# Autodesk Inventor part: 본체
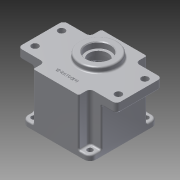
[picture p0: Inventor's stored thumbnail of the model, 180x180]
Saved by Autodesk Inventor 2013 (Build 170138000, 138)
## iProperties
Created: 2015-07
Part Number: 본체
Material: 알루미늄 6061
Document SubType Name: Modeling
Designer: user
Density: 2.71 g/cm^3
Mass: 705.36 g
Surface Area: 672.968 cm^2
Volume: 260.28 cm^3
Author: user
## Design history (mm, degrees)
sketch "스케치1"
  geometry: L1 (-65, 30)-(65, 30); L2 (65, 30)-(65, -30); L3 (65, -30)-(-65, -30); L4 (-65, -30)-(-65, 30); L5 (-30, 45)-(30, 45); L6 (30, 45)-(30, -45); L7 (30, -45)-(-30, -45); L8 (-30, -45)-(-30, 45); 5 further points
  constraints: 16 end point, 4 midpoint, 4 parallel, 2 horizontal, 2 horizontal alignment, 2 perpendicular, 2 vertical alignment
  dimensions: "d0" = 130 distance of L2.end L3.end; "d1" = 60 distance of L1.end L2.end; "d2" = 60 distance of L6.end L7.end; "d3" = 90 distance of L5.end L6.end
extrude "돌출1" new body sketch "스케치1" distance "d4" = 12; taper "d5" = 0 deg
sketch "스케치2"
  geometry: L1 (-45, -45)-(45, -45); L2 (45, -45)-(45, 45); L3 (45, 45)-(-45, 45); L4 (-45, 45)-(-45, -45); 3 further points
  constraints: 8 end point, 2 midpoint, 2 parallel, 1 horizontal, 1 horizontal alignment, 1 perpendicular, 1 vertical alignment
  dimensions: "d6" = 90 distance of L3.end L2.end; "d7" = 90 distance of L2.end L1.end
extrude "돌출2" join sketch "스케치2" distance "d8" = 58; taper "d9" = 0 deg
sketch "스케치3"
  geometry: L1 (30, 45)-(30, 30) reference; L2 (-45, -45)-(-45, -30) reference; L3 (-30, -30)-(-45, -30) reference; L4 (-30, -45)-(-30, -30) reference; L5 (30, -45)-(-30, -45) reference; L6 (30, -30)-(30, -45) reference; L7 (45, -30)-(30, -30) reference; L8 (45, 30)-(45, -30) reference; L9 (45, 30)-(65, 30) reference; L10 (65, 30)-(65, -30) reference; L11 (65, -30)-(45, -30) reference; L12 (45, -30)-(45, -45) reference; L13 (45, -45)-(30, -45) reference; L14 (-30, -45)-(-45, -45) reference; L15 (-45, -30)-(-45, 30) reference; L16 (-65, 30)-(-45, 30) reference; L17 (-65, -30)-(-65, 30) reference; L18 (-45, -30)-(-65, -30) reference; L19 (45, 45)-(45, 30) reference; L20 (30, 30)-(45, 30) reference; L21 (30, 45)-(30, 30) reference; L22 (30, 45)-(45, 45) reference; L23 (-45, 30)-(-45, 45) reference; L24 (-45, 45)-(-30, 45) reference; L25 (-30, 45)-(30, 45) reference; L26 (-45, 30)-(-30, 30) reference; L27 (-30, 30)-(-30, 45) reference; 1 further point
extrude "돌출3" cut sketch "스케치3" distance "d10" = 51; taper "d11" = 0 deg
sketch "스케치4"
  geometry: C1 r 40 at (0, 0); 1 further point
  constraints: 1 centre point, 1 coincident
  dimensions: "d12" = 80 diameter of C1
extrude "돌출4" cut sketch "스케치4" distance "d13" = 9; taper "d14" = 0 deg
sketch "스케치5"
  geometry: C1 r 40 at (0, 0) reference; C2 r 39 at (0, 0)
  constraints: 1 centre point, 1 coincident
  dimensions: "d15" = 78 diameter of C2
extrude "돌출5" cut sketch "스케치5" distance "d16" = 52; taper "d17" = 0 deg
sketch "스케치6"
  geometry: L1 (30, -45)-(30, -30) reference; L2 (0, 0)-(0, 11); C1 r 25 at (0, 11)
  constraints: 2 end point, 1 centre point, 1 parallel
  dimensions: "d18" = 50 diameter of C1; "d19" = 11 distance of L2.end L2.start
extrude "돌출6" join sketch "스케치6" distance "d21" = 7; taper "d22" = 0 deg
sketch "스케치7"
  geometry: L1 (0, 0)-(0, 11); L2 (0, 0)-(0, -20); C1 r 39 at (0, 0) reference; A1 r 20.5 centre (0, 11) between (7.402, -8.117) and (-7.402, -8.117); A2 r 14 centre (0, -20) between (-7.402, -8.117) and (7.402, -8.117)
  constraints: 4 end point, 4 point on circle, 2 centre point, 2 coincident, 1 collinear, 1 vertical
  dimensions: "d23" = 11 distance of L1.start L1.end; "d24" = 41 diameter of A1; "d25" = 20 distance of L1.start L2.end; "d26" = 28 diameter of A2
extrude "돌출7" join sketch "스케치7" distance "d27" = 7; taper "d28" = 0 deg
sketch "스케치8"
  geometry: C1 r 25 at (0, 0) reference; C2 r 16 at (0, 0); 1 further point
  constraints: 1 centre point, 1 coincident
  dimensions: "d29" = 32 diameter of C2
extrude "돌출8" cut sketch "스케치8" distance "d30" = 8; taper "d31" = 0 deg
sketch "스케치9"
  geometry: C1 r 16 at (0, 0) reference; C2 r 12.5 at (0, 0); 1 further point
  constraints: 1 centre point, 1 coincident
  dimensions: "d32" = 25 diameter of C2
extrude "돌출9" cut sketch "스케치9" distance "d33" = 5; taper "d34" = 0 deg
sketch "스케치10"
  geometry: C1 r 17.5 at (0, 11); A1 r 20.5 centre (0, 11) between (7.402, -8.117) and (-7.402, -8.117) reference; 1 further point
  constraints: 1 centre point, 1 coincident
  dimensions: "d35" = 35 diameter of C1
extrude "돌출10" cut sketch "스케치10" distance "d36" = 10; taper "d37" = 0 deg
sketch "스케치11"
  geometry: C1 r 11 at (0, -20); A1 r 14 centre (0, -20) between (-7.402, -8.117) and (7.402, -8.117) reference; 1 further point
  constraints: 1 centre point, 1 coincident
  dimensions: "d38" = 22 diameter of C1
extrude "돌출11" cut sketch "스케치11" distance "d39" = 7; taper "d40" = 0 deg
sketch "스케치12"
  geometry: C1 r 11 at (0, 0) reference; C2 r 9.5 at (0, 0); 1 further point
  constraints: 1 centre point, 1 coincident
  dimensions: "d41" = 19 diameter of C2
extrude "돌출12" cut sketch "스케치12" distance "d42" = 1; taper "d43" = 0 deg
sketch "스케치13"
  geometry: L1 (0, 0)-(24.749, 24.749); L2 (0, 0)-(35, 0); L3 (0, 0)-(24.749, -24.749); L4 (0, 0)-(35, 0); L5 (0, 0)-(-24.749, 24.749); L6 (0, 0)-(-24.749, -24.749); L7 (0, 0)-(0, -14.324); L8 (0, 0)-(-22.714, 0); C1 r 40 at (0, 0) reference; C2 r 4 at (24.749, 24.749); C3 r 4 at (-24.749, -24.749); C4 r 4 at (24.749, -24.749); C5 r 4 at (-24.749, 24.749); A1 r 39 centre (0, 0) between (21.134, 32.777) and (32.777, 21.134) reference; A2 r 3.5 centre (19.238, 29.836) between (21.762, 27.412) and (21.134, 32.777); A3 r 3.5 centre (29.836, 19.238) between (32.777, 21.134) and (27.412, 21.762); A4 r 3.5 centre (29.836, -19.238) between (27.412, -21.762) and (32.777, -21.134); A5 r 3.5 centre (19.238, -29.836) between (21.134, -32.777) and (21.762, -27.412); A6 r 3.5 centre (-29.836, -19.238) between (-32.777, -21.134) and (-27.412, -21.762); A7 r 3.5 centre (-19.238, -29.836) between (-21.762, -27.412) and (-21.134, -32.777); A8 r 3.5 centre (-29.836, 19.238) between (-27.412, 21.762) and (-32.777, 21.134); A9 r 3.5 centre (-19.238, 29.836) between (-21.134, 32.777) and (-21.762, 27.412); A10 r 35 centre (0, 0) between (-27.412, -21.762) and (-21.762, -27.412); A11 r 35 centre (0, 0) between (21.762, -27.412) and (27.412, -21.762); A12 r 35 centre (0, 0) between (27.412, 21.762) and (21.762, 27.412); A13 r 35 centre (0, 0) between (-21.762, 27.412) and (-27.412, 21.762); A14 r 39 centre (0, 0) between (21.134, -32.777) and (32.777, -21.134); A15 r 39 centre (0, 0) between (32.777, 21.134) and (21.134, 32.777); A16 r 39 centre (0, 0) between (-21.134, 32.777) and (-32.777, 21.134); A17 r 39 centre (0, 0) between (-32.777, -21.134) and (-21.134, -32.777)
  constraints: 38 point on circle, 20 centre point, 18 symmetric about line, 16 end point, 5 tangent, 3 coincident, 3 perpendicular, 2 equal length, 2 horizontal, 1 collinear, 6 other
  dimensions: "d45" = 8 diameter of C2; "d46" = 45 deg angle of L2 L1; "d47" = 8 diameter of C3; "d48" = 45 deg angle of L3 L4; "d49" = 8 diameter of C4; "d50" = 8 diameter of C5; "d51" = 7 diameter of A2; "d52" = 7 diameter of A3; "d53" = 10.12841 distance from line of L7.end L1; "d54" = 16.06109 distance from line of L8.end L1
extrude "돌출13" join sketch "스케치13" stored distance "d55" = 1; taper "d56" = 0 deg
fillet "모깎기1" dims "d57" = 3
fillet "모깎기2" dims "d58" = 0.3
fillet "모깎기3" dims "d59" = 0.3
fillet "모깎기4" dims "d60" = 2
chamfer "모따기1" distance "d61" = 1; stored, may be unused: second distance "d62" = 2, angle "d63" = 45 deg
fillet "모깎기5" dims "d64" = 8
fillet "모깎기6" dims "d65" = 5
fillet "모깎기7" dims "d66" = 5
sketch "스케치14"
  geometry: L1 (-37, -37)-(37, -37); L2 (37, -37)-(37, 37); L3 (37, 37)-(-37, 37); L4 (-37, 37)-(-37, -37); C1 r 3.5 at (37, 37); C2 r 3.5 at (37, -37); C3 r 3.5 at (-37, -37); C4 r 3.5 at (-37, 37); 3 further points
  constraints: 8 end point, 4 centre point, 4 coincident, 2 midpoint, 2 parallel, 1 horizontal, 1 horizontal alignment, 1 perpendicular, 1 vertical alignment
  dimensions: "d67" = 74 distance of L3.end L2.end; "d68" = 74 distance of L2.end L1.end; "d69" = 7 diameter of C1; "d70" = 7 diameter of C2; "d71" = 7 diameter of C3; "d72" = 7 diameter of C4
extrude "돌출14" cut sketch "스케치14" distance "d73" = 20; taper "d74" = 0 deg
sketch "스케치15"
  geometry: L1 (-55, -17.5)-(55, -17.5); L2 (55, -17.5)-(55, 17.5); L3 (55, 17.5)-(-55, 17.5); L4 (-55, 17.5)-(-55, -17.5); C1 r 4.5 at (-55, 17.5); C2 r 4.5 at (-55, -17.5); C3 r 4.5 at (55, -17.5); C4 r 4.5 at (55, 17.5); 3 further points
  constraints: 8 end point, 4 centre point, 4 coincident, 2 midpoint, 2 parallel, 1 horizontal, 1 horizontal alignment, 1 perpendicular, 1 vertical alignment
  dimensions: "d75" = 110 distance of L3.end L2.end; "d76" = 35 distance of L2.end L1.end; "d77" = 9 diameter of C1; "d78" = 9 diameter of C2; "d79" = 9 diameter of C3; "d80" = 9 diameter of C4
extrude "돌출15" cut sketch "스케치15" distance "d81" = 20; taper "d82" = 0 deg
sketch "스케치16"
  geometry: A1 r 4 centre (-24.749, -24.749) between (-21.763, -27.411) and (-27.411, -21.763) reference; A2 r 4 centre (-24.749, 24.749) between (-27.411, 21.763) and (-21.763, 27.411) reference; A3 r 4 centre (24.749, 24.749) between (21.763, 27.411) and (27.411, 21.763) reference; A4 r 4 centre (24.749, -24.749) between (27.411, -21.763) and (21.763, -27.411) reference
hole "구멍1" sketch "스케치16" at (-24.749, 24.749), (24.749, 24.749), (24.749, -24.749), (-24.749, -24.749) diameter "d83" = 3.459; stored, may be unused: countersink angle "d87" = 90 deg, drill point angle "d89" = 118 deg; dims "d84" = 12, "d85" = 4, "d86" = 2, "d88" = 15
fillet "모깎기8" dims "d90" = 2
fillet "모깎기13" dims "d95" = 2
fillet "모깎기14" dims "d96" = 2
sketch "스케치17"
  geometry: L1 (-30, -45)-(30, -45) reference; C1 r 27 at (0, 11) reference; 4 further points
  constraints: 1 vertical alignment, 1 other
  dimensions: "d97" = 15 distance from line of L1 point (0, -30)
feature "엠보싱1" sketch "스케치17" dims "d98" = 0.5, "d99" = 0
fillet "모깎기21" dims "d106" = 2
fillet "모깎기22" dims "d107" = 2
node "솔리드1"
node "절단 모서리 투영1"
